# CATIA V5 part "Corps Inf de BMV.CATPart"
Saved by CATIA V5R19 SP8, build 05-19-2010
Part number: Corps Inf de BMV
Nomenclature: 70_a
Bounding box of the stored display mesh (mm): x -32.5 to 87.508, y -34 to 42.238, z -35.8 to 29.3
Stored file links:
  C:\Users\rphgr\Desktop\0_Tapis_TC520B_vitesse\Corps Inf de BMV.CATPart
  D:\Programmes\DassaultSysteme\win_b64\reffiles\standard\MetricThickPitch.txt
  C:\Users\rphgr\Desktop\0_Tapis_TC520B_vitesse\CE_Boitier_Moteur_Vis.CATProduct
  D:\Documents\1_Travail\1 - ac-limoges.fr\ac-limoges.fr\Emmanuel Maynard - STI2D_Turgot\3 - Supports\Tapis de course TC520B\Tapis de course TC520B_Ca\Bloc moteur_vis\Roue_2-3.CATPart
  D:\Documents\1_Travail\1 - ac-limoges.fr\ac-limoges.fr\Emmanuel Maynard - STI2D_Turgot\3 - Supports\Tapis de course TC520B\Tapis de course TC520B_Ca\Bloc moteur_vis\Roue_9-10.CATPart
  D:\Documents\1_Travail\1 - ac-limoges.fr\ac-limoges.fr\Emmanuel Maynard - STI2D_Turgot\3 - Supports\Tapis de course TC520B\Tapis de course TC520B_Ca\Roue_11.CATPart
  D:\Documents\1_Travail\1 - ac-limoges.fr\ac-limoges.fr\Emmanuel Maynard - STI2D_Turgot\3 - Supports\GrabCAD\Tapis de course TC520B\Tapis de course TC520B\Part1.CATPart
  D:\Documents\1_Travail\1 - ac-limoges.fr\ac-limoges.fr\Emmanuel Maynard - STI2D_Turgot\3 - Supports\Tapis de course TC520B\Tapis de course TC520B_Ca\Roue_4.CATPart
  D:\Documents\1_Travail\1 - ac-limoges.fr\ac-limoges.fr\Emmanuel Maynard - STI2D_Turgot\3 - Supports\Tapis de course TC520B\Tapis de course TC520B_Ca\Bloc moteur_vis\Roue_5-6.CATPart
  D:\Documents\1_Travail\1 - ac-limoges.fr\ac-limoges.fr\Emmanuel Maynard - STI2D_Turgot\3 - Supports\Tapis de course TC520B\Tapis de course TC520B_Ca\Roue_3.CATPart
  D:\Documents\1_Travail\1 - ac-limoges.fr\ac-limoges.fr\Emmanuel Maynard - STI2D_Turgot\3 - Supports\Tapis de course TC520B\Tapis de course TC520B_Ca\Roue_6.CATPart
  D:\Documents\1_Travail\1 - ac-limoges.fr\ac-limoges.fr\Emmanuel Maynard - STI2D_Turgot\3 - Supports\Tapis de course TC520B\Tapis de course TC520B_Ca\Roue_7.CATPart
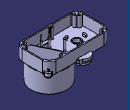
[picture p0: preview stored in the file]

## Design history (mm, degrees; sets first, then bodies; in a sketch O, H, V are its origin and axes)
Set1
  DatumCurve1 to DatumCurve3: linked copy from another document
Set2
  DatumCurve4 to DatumCurve9
Body1 (main body)
  AxisSystem1: origin (0, 0, 0), X (1, 0, 0), Y (0, 1, 0), Z (0, 0, 1)
  Sketch1 on XY plane of AxisSystem1, origin (0, 0, 0), H (1, 0, 0), V (0, 1, 0)
    line L1 (-19.5, 32.5) -> (72.5, 32.5)
    line L2 (85.5, 19.5) -> (85.5, -19.5)
    line L3 (72.5, -32.5) -> (-19.5, -32.5)
    line L4 (-32.5, -19.5) -> (-32.5, 19.5)
    arc A1 centre (-19.5, 19.5) radius 13 from (-19.5, 32.5) to (-32.5, 19.5) ccw
    arc A2 centre (-19.5, -19.5) radius 13 from (-19.5, -32.5) to (-32.5, -19.5) cw
    arc A3 centre (72.5, -19.5) radius 13 from (85.5, -19.5) to (72.5, -32.5) cw
    arc A4 centre (72.5, 19.5) radius 13 from (72.5, 32.5) to (85.5, 19.5) cw
    distance L1 L3 = 65
    distance L4 L2 = 118
    radius A1 = 13
    radius A2 = 13
    radius A3 = 13
    radius A4 = 13
    distance O L3 = 32.5
    distance L4 V = 32.5
    horizontal: L1 H, L3 H
    vertical: L2 V, L4 V
    tangency: A1 L1, A1 L4, A2 L3, A2 L4, A3 L2, A3 L3, A4 L1, A4 L2
  Pad1: profile Sketch1, direction (0, 0, 1), length 22
  Sketch2 on end face of Pad1, origin (91.0803, -4.9021, 22), H (1, 0, 0), V (0, 1, 0)
    point P1 (-15.5803, -21.5979)
    reference intersected line E1 (-2.5209, -27.5979) -> (-94.5209, -27.5979) from face of Pad1 from Sketch1.L3
    reference intersected line E2 (-5.5803, 39) -> (-5.5803, 0) from face of Pad1 from Sketch1.L2
    distance P1 E1 = 6
    distance P1 E2 = 10
  Hole1: placed by Sketch2, at (75.5, -26.5, 22) direction (0, 0, -1), diameter 3.242, depth 19.5, V-bottom angle 120, threaded "M4", thread diameter 4, thread depth 16, pitch 0.7
  Sketch3, origin (-5.9197, -4.9021, 22), H (1, 0, 0), V (0, 1, 0)
    point P1 (-16.5803, -21.5979)
    reference intersected line E1 (77.4197, -27.5979) -> (-14.5803, -27.5979) from face of Pad1 from Sketch1.L3
    reference intersected line E2 (-26.5803, -14.5979) -> (-26.5803, 24.4021) from face of Pad1 from Sketch1.L4
    distance P1 E1 = 6
    distance E2 P1 = 10
  Hole2: placed by Sketch3, at (-22.5, -26.5, 22) direction (0, 0, -1), diameter 3.242, depth 19.5, V-bottom angle 120, threaded "M4", thread diameter 4, thread depth 16, pitch 0.7
  Sketch4, origin (152.5295, 25.5665, 22), H (1, 0, 0), V (0, 1, 0)
    point P1 (-95.0295, 2.9335)
    reference intersected line E1 (-173.0295, 6.9335) -> (-81.0295, 6.9335) from face of Pad1 from Sketch1.L1
    reference intersected line E2 (-67.0295, -6.0665) -> (-67.0295, -45.0665) from face of Pad1 from Sketch1.L2
    distance P1 E1 = 4
    distance P1 E2 = 28
  Hole3: placed by Sketch4, at (57.5, 28.5, 22) direction (0, 0, -1), diameter 3.242, depth 19.5, V-bottom angle 120, threaded "M4", thread diameter 4, thread depth 16, pitch 0.7
  Sketch5, origin (38.0803, -4.9021, 22), H (1, 0, 0), V (0, 1, 0)
    point P1 (-17.5803, -23.5979)
    reference intersected line E1 (33.4197, -27.5979) -> (-58.5803, -27.5979) from face of Pad1 from Sketch1.L3
    reference projected point E2 (37.4197, -21.5979) from axis of face of Hole1
    distance P1 E1 = 4
    distance P1 E2 H = 55
  Hole4: placed by Sketch5, at (20.5, -28.5, 22) direction (0, 0, -1), diameter 3.242, depth 19.5, V-bottom angle 120, threaded "M4", thread diameter 4, thread depth 16, pitch 0.7
  Sketch6, origin (116.5295, 25.5665, 22), H (1, 0, 0), V (0, 1, 0)
    point P1 (-99.0295, 2.9335)
    reference intersected line E1 (-137.0295, 6.9335) -> (-45.0295, 6.9335) from face of Pad1 from Sketch1.L1
    reference projected point E2 (-59.0295, 2.9335) from axis of face of Hole3
    distance P1 E1 = 4
    distance P1 E2 H = 40
  Hole5: placed by Sketch6, at (17.5, 28.5, 22) direction (0, 0, -1), diameter 3.242, depth 19.5, V-bottom angle 120, threaded "M4", thread diameter 4, thread depth 16, pitch 0.7
  Sketch7 on end face of Pad1, origin (73.5295, 25.5665, 22), H (1, 0, 0), V (0, 1, 0)
    point P1 (-96.0295, 0.9335)
    reference intersected line E1 (-94.0295, 6.9335) -> (-2.0295, 6.9335) from face of Pad1 from Sketch1.L1
    reference intersected line E2 (-106.0295, -45.0665) -> (-106.0295, -6.0665) from face of Pad1 from Sketch1.L4
    distance P1 E1 = 6
    distance P1 E2 = 10
  Hole6: placed by Sketch7, at (-22.5, 26.5, 22) direction (0, 0, -1), diameter 3.242, depth 19.5, V-bottom angle 120, threaded "M4", thread diameter 4, thread depth 16, pitch 0.7
  Sketch8 on end face of Pad1, origin (0, 0, 22), H (1, 0, 0), V (0, 1, 0)
    circle A1 centre (-26.5, -22.0279) radius 2
    point P1 (-26.5, -22.0279)
    circle A2 centre (51.5, 28.5) radius 2
    point P2 (51.5, 28.5)
    reference intersected line E1 (-20.5, 32.5) -> (71.5, 32.5) from face of Pad1 from Sketch1.L1
    reference projected point E2 (57.5, 28.5) from axis of face of Hole3
    reference projected point E3 (-22.5, -26.5) from Sketch3
    reference intersected line E4 (-32.5, -19.5) -> (-32.5, 19.5) from face of Pad1 from Sketch1.L4
    radius A2 = 2
    distance E1 P2 = 4
    distance P2 E2 = 6
    radius A1 = 2
    distance P1 E3 = 6
    distance P1 E4 = 6
  Pocket1: profile Sketch8, direction (0, 0, -1), length 20
  Shell1: IntOffset 2, Face end face of Pad1, ExtOffset 0
  Sketch9 on end face of Pocket1, origin (0, 0, 2), H (1, 0, 0), V (0, 1, 0)
    projected circle E1 centre (51.5, 28.5) radius 2 from end face of Pocket1
    projected circle E2 centre (-26.5, -22.0279) radius 2 from end face of Pocket1
  Pad2: profile Sketch9, direction (0, 0, 1), up to end face of Pad1, offset 3
  Sketch10 on face of Shell1, origin (0, 0, 2), H (1, 0, 0), V (0, 1, 0)
  Pad3: profile Sketch10, direction (0, 0, 1), up to end face of Pad1
  ThickSurface1: Surface face of Shell1, TopOffset 2, BotOffset 0
  Sketch11 on face of Pad1, origin (0, 0, 22), H (1, 0, 0), V (0, 1, 0)
    line L1 (51.1851, 24.5124) -> (73.5591, -22.428)
    point P1 (51.1851, 24.5124)
    reference projected circle E1 centre (51.5, 28.5) radius 2 from edge [end face of Pad1 | face of Pocket1 from Sketch8.A2]
    reference projected point E2 (75.5, -26.5) from axis of face of Hole1
    reference projected arc E3 centre (51.5, 28.5) radius 4 from (48.0359, 30.5) to (54.7407, 26.1552) ccw from edge [face of Shell1 | end face of Pad1]
    length L1 = 52
    tangency: L1 E1
    coincidence: L1 E2, P1 E3
  Stiffener1: ThicknessValue 1, ExtendedProfile Sketch11, ThicknessTop 0
  Sketch12 on face of Stiffener1, origin (50.7785, 24.2034, 0), H (0.4303, -0.9027, 0), V (0, 0, 1)
    line L1 (51.3206, 2) -> (51.3206, 17)
    line L2 (51.3206, 17) -> (47.8206, 22)
    line L3 (47.8206, 22) -> (52.8206, 22)
    line L4 (52.8206, 22) -> (52.8206, 2)
    line L5 (52.8206, 2) -> (51.3206, 2)
    reference projected line E1 (52.3903, 2) -> (-0.8759, 2) from edge [face of Stiffener1 | face of Shell1]
    reference projected line E2 (52.8206, 22) -> (52.8206, 2) from edge [face of Stiffener1 | face of Shell1]
    reference intersected line E3 (-9.6211, 22) -> (61.342, 22) from face of Pad1
    distance L1 L4 = 1.5
    length L3 H = 5
    length L1 = 15
    vertical: L1 V, L4 V
    horizontal: L3 H, L5 H
    coincidence: E1 L5, L4 E2, L3 E3
  Pocket2: profile Sketch12, direction (0.9027, 0.4303, 0), through (limit type 6)
  Plane1: type Offset, RefPlane face of Pocket2, Offset 8, reversed
  Sketch13 on face of Pocket2, origin (0, 0, 2), H (1, 0, 0), V (0, 1, 0)
    circle A1 centre (0, 0) radius 8
    circle A2 centre (53.4623, 0) radius 4.5
    point P1 (53.4623, 0)
    radius A1 = 8
    radius A2 = 4.5
    coincidence: P1 H
  Pocket3: profile Sketch13, direction (0, 0, -1), through (limit type 3)
  Sketch14 on start face of Pad1, origin (0, 0, 0), H (1, 0, 0), V (0, -1, 0)
    circle A1 centre (53.4623, 0) radius 11
    point P1 (53.4623, 0)
    reference projected point E1 (53.4623, 0) from axis of face of Pocket3 from Sketch13.A2
    radius A1 = 11
    coincidence: P1 H
    concentricity: A1 E1
  Pocket4: profile Sketch14, direction (0, 0, 1), length 0.6
  Sketch15 on start face of Pad1, origin (0, 0, 0), H (1, 0, 0), V (0, -1, 0)
    circle A1 centre (53.4623, 0) radius 11
    circle A2 centre (53.4623, 0) radius 13.5
    reference projected circle E1 centre (53.4623, 0) radius 11 from edge [start face of Pad1 | face of Pocket4 from Sketch14.A1]
    distance A2 A1 = 2.5
    coincidence: A1 E1
  Pad4: profile Sketch15, direction (0, 0, -1), length 9
  Sketch16 on face of Pocket2, origin (0, 0, 2), H (1, 0, 0), V (0, 1, 0)
    circle A1 centre (51.2639, -17.5) radius 2
    point P1 (51.2639, -17.5)
    reference projected point E1 (51.2639, -17.5) from axis of face of Pad22 from Sketch45.A1
    radius A1 = 2
    coincidence: P1 E1
  Pad5: profile Sketch16, direction (0, 0, 1), length 17
  Draft1: PullDir face of Pocket2, Angle 1.5, SupportToDraft face of Pad5 from Sketch16.A1, Neutral face of Pocket2
  Sketch17 on face of Pocket2, origin (0, 0, 2), H (1, 0, 0), V (0, 1, 0)
    circle A1 centre (36.571, -16.2039) radius 2.5
    point P1 (36.571, -16.2039)
    reference projected point E1 (36.571, -16.2039) from axis of face of Pad21 from Sketch44.A1
    radius A1 = 2.5
    coincidence: P1 E1
  Pad6: profile Sketch17, direction (0, 0, 1), length 14.7
  Sketch18 on Plane1, origin (0, 0, 10), H (1, 0, 0), V (0, -1, 0)
    line L1 (71.6053, 19.2944) -> (36.571, 16.2039)
    line L2 (36.571, 16.2039) -> (30.4074, 20.9197)
    reference projected point E1 (20.5, 28.5) from axis of face of Shell1
    reference projected point E2 (36.571, 16.2039) from axis of face of Pad21 from Sketch44.A1
    reference projected point E3 (51.2639, 17.5) from axis of face of Pad22 from Sketch45.A1
    reference projected point E4 (36.571, 16.2039) from axis of face of Pad6 from Sketch17.A1
    coincidence: L2 E1, L1 E2, L1 E3, L2 E4
  Pad7: profile Sketch18, direction (0, 0, -1), up to the existing solid (limit type 2), thin wall 1
  Sketch19 on face of Pocket2, origin (0, 0, 2), H (1, 0, 0), V (0, 1, 0)
    arc A1 centre (0, 0) radius 16.5 from (-16.225, 3) to (-16.225, -3) ccw
    arc A2 centre (0, 0) radius 13.5 from (-13.1624, 3) to (-13.1624, -3) ccw
    line L1 (-16.225, 3) -> (-13.1624, 3)
    line L2 (-13.1624, -3) -> (-16.225, -3)
    radius A2 = 13.5
    distance A2 A1 = 3
    distance L2 L1 = 6
    distance L1 O = 3
    horizontal: L1 H, L2 H
  Pad8: profile Sketch19, direction (0, 0, 1), length 4
  CircPattern1: of Pad8, instances 3, angular step 120 {= 360.0*1 deg/CircPattern1.AngularNumber}, axis from face of Pocket3 from Sketch13.A1
  Sketch20 on face of Pocket2, origin (0, 0, 2), H (1, 0, 0), V (0, 1, 0)
    circle A1 centre (67.395, 17.1706) radius 6.25
    radius A1 = 6.25
  Pocket5: profile Sketch20, direction (0, 0, -1), through (limit type 3)
  Sketch21 on start face of Pad1, origin (0, 0, 0), H (1, 0, 0), V (0, -1, 0)
    circle A1 centre (32.3481, -8.7093) radius 4
    point P1 (32.3481, -8.7093)
    reference projected point E1 (32.3481, -8.7093) from axis of face of Pad20 from Sketch43.A1
    radius A1 = 4
    coincidence: P1 E1
  Pad9: profile Sketch21, direction (0, 0, -1), length 6
  Fillet1: radius 0.5, on edge [face of Pad9 from Sketch21.A1 | end face of Pad9]
  Sketch22 on start face of Pad1, origin (0, 0, 0), H (1, 0, 0), V (0, -1, 0)
    arc A1 centre (53.4623, 0) radius 31 from (24.4623, -10.9545) to (24.4623, 10.9545) ccw
    point P1 (53.4623, 0)
    reference projected point E1 (53.4623, 0) from axis of face of Pad4 from Sketch15.A2
    line L1 (24.4623, 10.9545) -> (24.4623, -10.9545)
    radius A1 = 31
    distance L1 A1 = 60
    coincidence: P1 E1
    vertical: L1 V
  Pad10: profile Sketch22, direction (0, 0, -1), length 35.8, thin wall 1, second thickness 3
  Sketch23 on end face of Pad10, origin (0, 0, -35.8), H (1, 0, 0), V (0, -1, 0)
  Pocket6: profile Sketch23, direction (0, 0, 1), length 4
  Sketch24 on start face of Pad1, origin (0, 0, 0), H (1, 0, 0), V (0, -1, 0)
    line L1 (41.8457, -4.7917) -> (32.3481, -8.7093)
    point P2 (32.3481, -8.7093)
    line L2 (32.3481, -8.7093) -> (24.5121, -8.7093)
    reference projected point E1 (32.3481, -8.7093) from axis of face of Pad9 from Sketch21.A1
    reference projected point E2 (53.4623, 0) from axis of face of Pad4 from Sketch15.A2
    horizontal: L2 H
    coincidence: P2 E1, L1 E2
  Pad11: profile Sketch24, direction (0, 0, -1), length 4, thin wall 2, second thickness 3
  Sketch25 on start face of Pad1, origin (0, 0, 0), H (1, 0, 0), V (0, -1, 0)
    circle A1 centre (0, 0) radius 17
    circle A2 centre (0, 0) radius 14.6
    circle A3 centre (0, 0) radius 11
    circle A4 centre (0, 0) radius 6.7
    radius A1 = 17
    distance A2 A1 = 2.4
    radius A3 = 11
    radius A4 = 6.7
  Pad12: profile Sketch25, direction (0, 0, -1), length 9
  Sketch26 on end face of Pad12, origin (0, 0, -9), H (1, 0, 0), V (0, -1, 0)
    line L1 (9.773, 5.0487) -> (13.1078, 6.43)
    point P1 (9.773, 5.0487)
    point P2 (13.1078, 6.43)
    reference projected circle E1 centre (0, 0) radius 14.6 from edge [end face of Pad12 | face of Pad12 from Sketch25.A2]
    reference projected circle E2 centre (0, 0) radius 11 from edge [face of Pad12 from Sketch25.A3 | end face of Pad12]
    angle L1 H = 22.5
    coincidence: P2 E1, P1 E2
  Stiffener2: ThicknessValue 1.8, ExtendedProfile Sketch26, ThicknessTop 0
  CircPattern2: of Stiffener2, instances 8, angular step 45 {= 360.0*1 deg/CircPattern2.AngularNumber}, axis from face of Pad12 from Sketch25.A4
  Sketch27 on start face of Pad1, origin (0, 0, 0), H (1, 0, 0), V (0, -1, 0)
    arc A1 centre (0, 0) radius 21.665 from (17.4623, 12.8234) to (17.4623, -12.8234) ccw
    point P1 (17.4623, 12.8234)
    point P2 (17.4623, -12.8234)
    reference intersected line E1 (21.4623, -11.5022) -> (21.4623, 11.5022) from face of Pad10
    reference intersected line E2 (21.4623, -11.5022) -> (21.4623, 11.5022) from face of Pad10
    radius A1 = 21.665
    distance P1 E1 = 4
    distance P2 E2 = 4
  Pad13: profile Sketch27, direction (0, 0, -1), length 8, thin wall 0.9, second thickness 3
  Sketch28 on start face of Pad1, origin (0, 0, 0), H (1, 0, 0), V (0, -1, 0)
    arc A1 centre (17.715, -29.7385) radius 12.5 from (30.1626, -28.5955) to (13.433, -17.9948) ccw
    point P1 (17.715, -29.7385)
    arc A2 centre (32.4216, -35.5139) radius 2.5 from (32.3587, -38.0131) to (34.3869, -33.9688) ccw
    point P2 (32.4216, -35.5139)
    arc A3 centre (3.0084, -23.9631) radius 2.0362 from (2.3109, -22.0501) to (1.6607, -25.4895) ccw
    point P3 (3.0084, -23.9631)
    axis line L1 (3.0084, -23.9631) -> (32.4216, -35.5139)
    reference projected arc E1 centre (0, 0) radius 22.115 from (17.825, 13.0898) to (17.825, -13.0898) ccw from edge [start face of Pad1 | face of Pad13]
    reference projected curve E2 from edge [start face of Pad1 | face of Pad10]
    reference projected arc E3 centre (0, 0) radius 22.115 from (17.825, 13.0898) to (17.825, -13.0898) ccw from edge [start face of Pad1 | face of Pad13]
    line L2 (32.3587, -38.0131) -> (27.1971, -37.8833)
    line L3 (2.3109, -22.0501) -> (13.433, -17.9948)
    line L4 (34.3869, -33.9688) -> (30.1626, -28.5955)
    line L5 (1.6607, -25.4895) -> (5.2609, -28.6679)
    point P11 (5.2609, -28.6679)
    arc A4 centre (17.715, -29.7385) radius 12.5 from (5.2609, -28.6679) to (27.1971, -37.8833) ccw
    radius A1 = 12.5
    radius A2 = 2.5
    distance P3 P2 = 31.6
    radius A3 = 2.0362
    angle L2 L1 = 20
    angle L4 L1 = 30.3864
    angle L5 L1 = 20
    midpoint: L1 P1
    tangency: A3 E1, A1 E2, A1 E3, L3 A1, L3 A3, L4 A2, L2 A2, L5 A3
    coincidence: P11 A1, A1 A4
  Pad14: profile Sketch28, direction (0, 0, -1), length 2.7
  Sketch29 on start face of Pad14, origin (0, 0, 0), H (1, 0, 0), V (0, 1, 0)
  Pad15: profile Sketch29, direction (0, 0, 1), length 4.3
  Sketch30 on end face of Pad14, origin (0, 0, -2.7), H (1, 0, 0), V (0, -1, 0)
    circle A1 centre (17.715, -29.7385) radius 9.75
    reference projected arc E1 centre (17.715, -29.7385) radius 12.5 from (5.5238, -32.5) to (27.1971, -37.8833) ccw from edge [face of Pad15 | face of Pad14 from Sketch28.A4]
    radius A1 = 9.75
    concentricity: A1 E1
  Pocket7: profile Sketch30, direction (0, 0, 1), up to start face of Pad1
  Sketch31 on end face of Pad14, origin (0, 0, -2.7), H (1, 0, 0), V (0, -1, 0)
    projected circle E1 centre (17.715, -29.7385) radius 9.75 from edge [end face of Pad14 | face of Pocket7 from Sketch30.A1]
  Pad16: profile Sketch31, direction (0, 0, -1), length 4.3, thin wall 0, second thickness 1.3
  Plane2: type Normal, Curve {line type PtPt, FirstPoint {point type Center, Curve edge [end face of Pocket7 | face of Pad16]}, SecondPoint {point type Center, Curve edge [end face of Pocket4 | face of Pocket3 from Sketch13.A2]}}
  Sketch32 on Plane2, origin (13.7228, -11.4161, 0.2303), H (0.6395, 0.7688, 0), V (-0.0099, 0.0083, 0.9999)
    point P1 (34.1911, -3.7303)
    line L1 (37.9911, -0.2303) -> (37.9911, -7.2303)
    line L2 (37.9911, -7.2303) -> (30.3911, -7.2303)
    line L3 (30.3911, -7.2303) -> (30.3911, -0.2303)
    line L4 (30.3911, -0.2303) -> (37.9911, -0.2303)
    reference projected line E1 through (34.1911, 0) direction (0, -1) from axis of face of Pad16
    reference intersected line E2 (57.1284, -0.2303) -> (-27.4234, -0.2303) from start face of Pad1
    distance L1 L3 = 7.6
    distance L2 L4 = 7
    vertical: L1 V, L3 V
    horizontal: L2 H, L4 H
    equidistance: L1 L3 P1, L2 L4 P1
    coincidence: P1 E1, L4 E2
  Pocket8: profile Sketch32, direction (-0.7687, 0.6395, -0.0129), length 16.3
  Sketch33 on face of Pocket8 from Sketch32.L4, origin (0.0023, -0.0019, -0.2303), H (0.6395, 0.7688, 0), V (0.7687, -0.6395, 0.0129)
  Pocket9: profile Sketch33, direction (-0.0099, 0.0083, 0.9999), through (limit type 3)
  Sketch34 on end face of Pad14, origin (31.6384, 35.3883, -2.7), H (1, 0, 0), V (0, -1, 0)
    point P1 (0.7832, -0.1256)
    reference projected arc E1 centre (0.7832, -0.1256) radius 2.5 from (0.7204, -2.6248) to (2.7486, 1.4195) ccw from edge [face of Pad15 | face of Pad14 from Sketch28.A2]
    concentricity: P1 E1
  Hole7: placed by Sketch34, at (32.4216, 35.5139, -2.7) direction (0, 0, 1), diameter 2.459, through (limit type 3), threaded "M3", thread diameter 3, thread depth 7, pitch 0.5
  Sketch35 on end face of Pad14, origin (3.1634, 23.729, -2.7), H (1, 0, 0), V (0, -1, 0)
    point P1 (-0.1551, -0.234)
    reference projected point E1 (-0.1551, -0.234) from axis of face of Pad14 from Sketch28.A3
    coincidence: P1 E1
  Hole8: placed by Sketch35, at (3.0084, 23.9631, -2.7) direction (0, 0, 1), diameter 2.459, through (limit type 3), threaded "M3", thread diameter 3, thread depth 4.7, pitch 0.5
  Sketch36 on start face of Pad1, origin (0, 0, 0), H (1, 0, 0), V (0, -1, 0)
    axis line L1 (24.4149, 27.5) -> (82.5097, -27.5)
    point P2 (82.5097, -27.5)
    reference projected point E1 (53.4623, 0) from axis of face of Pad4
    arc A1 centre (24.4149, 27.5) radius 5 from (26.9046, 31.8361) to (20.0409, 25.0776) ccw
    arc A2 centre (82.5097, -27.5) radius 5 from (80.5213, -32.0876) to (86.9817, -25.2637) ccw
    point P3 (82.5097, -27.5)
    line L2 (86.9817, -25.2637) -> (82.8762, -17.0535)
    line L3 (80.5213, -32.0876) -> (72.0989, -28.4373)
    line L4 (20.0409, 25.0776) -> (24.2732, 17.4355)
    line L5 (26.9046, 31.8361) -> (33.9085, 27.8145)
    point P8 (33.9085, 27.8145)
    arc A3 centre (53.4623, 0) radius 34 from (33.9085, 27.8145) to (24.2732, 17.4355) ccw
    reference projected arc E2 centre (53.4623, 0) radius 34 from (63.4498, -32.5) to (84.5, -13.8802) ccw from edge [start face of Pad1 | face of Pad10]
    point P11 (33.9085, 27.8145)
    arc A4 centre (53.4623, 0) radius 34 from (72.0989, -28.4373) to (82.8762, -17.0535) ccw
    reference intersected line E3 (-20.5, 32.5) -> (71.5, 32.5) from face of Pad1 from Sketch1.L3
    length L1 = 80
    radius A2 = 5
    radius A1 = 5
    angle L4 L1 = 17.589
    angle L1 L5 = 13.5686
    angle L2 L1 = 20
    angle L1 L3 = 20
    midpoint: L1 E1
    tangency: L2 A2, L4 A1, L5 A1, L3 A2, A1 E3
    coincidence: A3 E2, L5 P11, A3 A4, P8 P11, P3 P2
  Pad17: profile Sketch36, direction (0, 0, -1), length 1.6
  Sketch37 on start face of Pad17, origin (0, 0, 0), H (1, 0, 0), V (0, 1, 0)
  Pad18: profile Sketch37, direction (0, 0, 1), length 6
  Sketch38 on end face of Pad17, origin (81.9652, 28.1923, -1.6), H (1, 0, 0), V (0, -1, 0)
    point P1 (0.5444, 0.6923)
    reference projected point E1 (0.5444, 0.6923) from axis of face of Pad17 from Sketch36.A2
    coincidence: P1 E1
  Hole9: placed by Sketch38, at (82.5097, 27.5, -1.6) direction (0, 0, 1), diameter 3.242, depth 12, threaded "M4", thread diameter 4, thread depth 12, pitch 0.7
  Sketch39 on end face of Pad17, origin (24.2839, -27.1816, -1.6), H (1, 0, 0), V (0, -1, 0)
    point P1 (0.131, 0.3184)
    reference projected point E1 (0.131, 0.3184) from axis of face of Pad17 from Sketch36.A1
    coincidence: P1 E1
  Hole10: placed by Sketch39, at (24.4149, -27.5, -1.6) direction (0, 0, 1), diameter 3.242, through (limit type 3), threaded "M4", thread diameter 4, thread depth 23.6, pitch 0.7
  Sketch40 on face of Pocket2, origin (0, 0, 2), H (1, 0, 0), V (0, 1, 0)
    circle A1 centre (24.4149, -27.5) radius 2.5
    point P1 (24.4149, -27.5)
    reference projected point E1 (24.4149, -27.5) from axis of face of Hole10
    radius A1 = 2.5
    coincidence: P1 E1
  Pad19: profile Sketch40, direction (0, 0, 1), length 4.5
  Sketch41 on start face of Pad19, origin (26.2656, -27.8408, 2), H (1, 0, 0), V (0, -1, 0)
    point P1 (-1.8507, -0.3408)
    reference projected point E1 (-1.8507, -0.3408) from axis of face of Hole10
    coincidence: P1 E1
  Hole11: placed by Sketch41, at (24.4149, -27.5, 2) direction (0, 0, 1), diameter 3.242, through (limit type 3), threaded "M4", thread diameter 4, thread depth 3.6, pitch 0.7
  Fillet2: radius 2, on edge [start face of Pad1 | face of Pad13]
  Fillet3: radius 0.2, on edge [start face of Pad1 | face of Pad10] (x3); edge [start face of Pad1 | face of Pad1 from Sketch1.L3] (x2); edge [start face of Pad1 | face of Pad17 from Sketch36.L5]; edge [face of Pad17 from Sketch36.A1 | end face of Pad17]; edge [start face of Pad1 | face of Pad17 from Sketch36.A1]; edge [face of Pad17 from Sketch36.L5 | face of Pad10]; edge [end face of Pad17 | face of Pad10]; edge [face of Pad10 | face of Pad17 from Sketch36.L4]; edge [start face of Pad1 | face of Pad14 from Sketch28.A4]; edge [start face of Pad1 | face of Pad14 from Sketch28.L5]; start face of Pad1 (x3); edge [face of Pad17 from Sketch36.A2 | end face of Pad17]; edge [face of Pad10 | end face of Pad17]; edge [face of Pad10 | face of Pad18]; edge [face of Pad18 | face of Pad10]; edge [start face of Pad1 | face of Pad1 from Sketch1.A3]
  Sketch42 on start face of Pad12, origin (0, 0, 0), H (1, 0, 0), V (0, 1, 0)
    projected circle E1 centre (0, 0) radius 8 from edge [face of Pocket3 from Sketch13.A1 | start face of Pad12]
    projected circle E2 centre (0, 0) radius 6.7 from edge [face of Pad12 from Sketch25.A4 | start face of Pad12]
  Pocket10: profile Sketch42, direction (0, 0, -1), length 6
Body2 "Axes rous"
  Sketch43 on face of Pocket2, origin (0, 0, 2), H (1, 0, 0), V (0, 1, 0)
    circle A1 centre (32.3481, 8.7093) radius 2.5
    point P1 (32.3481, 8.7093)
    reference projected point E1 (53.4623, 0) from axis of face of Pocket3 from Sketch13.A2
    reference projected point E2 (0, 0) from axis of face of Pocket10
    distance P1 E1 = 22.8399
    distance P1 E2 = 33.5
    radius A1 = 2.5
  Pad20 "Axe Roue 2-3": profile Sketch43, direction (0, 0, 1), length 24.4
  Sketch44 on face of Pocket2, origin (0, 0, 2), H (1, 0, 0), V (0, 1, 0)
    circle A1 centre (36.571, -16.2039) radius 1
    point P1 (36.571, -16.2039)
    reference projected point E1 (0, 0) from axis of face of Pocket10
    reference intersected line E2 through (0, -30.5) direction (-1, 0) from face of Shell1
    radius A1 = 1
    distance P1 E1 = 40
    distance P1 E2 = 14.2961
  Pad21 "Axe Roues 5-6 & 9-10": profile Sketch44, direction (0, 0, 1), length 24.3
  Sketch45 on face of Pocket2, origin (0, 0, 2), H (1, 0, 0), V (0, 1, 0)
    circle A1 centre (51.2639, -17.5) radius 1
    point P1 (51.2639, -17.5)
    reference projected point E1 (36.571, -16.2039) from axis of face of Pad21 from Sketch44.A1
    reference intersected line E2 through (0, -30.5) direction (-1, 0) from face of Shell1
    radius A1 = 1
    distance P1 E1 = 14.75
    distance P1 E2 = 13
  Pad22 "Axes Roues 7-8 &11": profile Sketch45, direction (0, 0, 1), length 27.3
  Fillet4: radius 0.5, on end face of Pad20; edge [face of Pad22 from Sketch45.A1 | end face of Pad22]; end face of Pad21
Body3 "bague"
  Sketch46 on end face of Pocket10, origin (0, 0, -6), H (1, 0, 0), V (0, 1, 0)
    circle A1 centre (0, 0) radius 8
    circle A2 centre (0, 0) radius 6
    reference projected circle E1 centre (0, 0) radius 8 from edge [end face of Pocket10 | face of Pocket10 from Sketch42.E1]
    radius A2 = 6
    coincidence: A1 E1
  Pad23: profile Sketch46, direction (0, 0, 1), length 8
  Fillet5: radius 0.5, on face of Pad23 from Sketch46.A1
